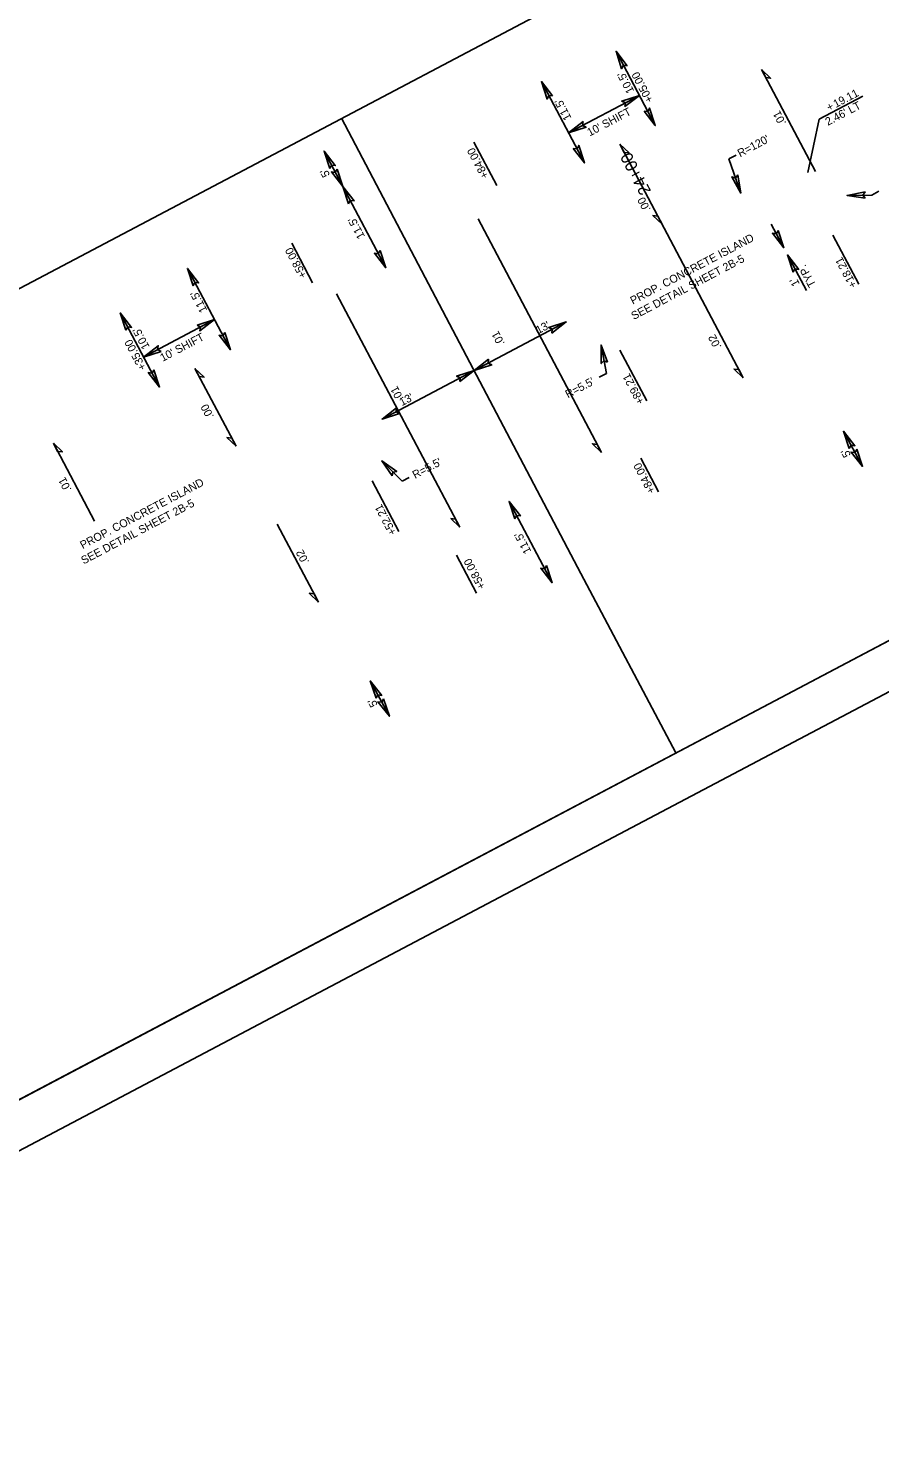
# Model space of a CAD drawing. Extents: x 1487555 to 1489555, y 497613 to 499367.
# Drawn here: x 1488347 to 1488773, y 497613 to 498320 of the extents above; entities that cross this region are included whole.
import ezdxf

# ---------------------------------------------------------------- set-up
doc = ezdxf.new("R2010")
doc.units = 0
for name, color, linetype in [('Old_Level_6', 7, 'Continuous'), ('Prop Dimension', 7, 'Continuous'), ('Prop Dimension Text', 7, 'Continuous'), ('Prop Horizontal Alignment Direction Label', 7, 'Continuous'), ('Prop Superelevation  Arrow CELL', 7, 'Continuous'), ('Prop Superelevation Label', 7, 'Continuous'), ('Prop Terminator CELL', 7, 'Continuous'), ('Sheet Plan CELL', 7, 'Continuous'), ('Sheet Plot Border Outside CELL', 7, 'Continuous')]:
    doc.layers.add(name, color=color, linetype=linetype)

msp = doc.modelspace()

# ---------------------------------------------------------------- linework, layer by layer
at = {"layer": 'Old_Level_6'}
msp.add_lwpolyline([(1488670.74, 497957.36), (1488623.31, 498047.13), (1488557.78, 498171.84), (1488503.78, 498274.53)], dxfattribs=at)
at = {"layer": 'Prop Dimension'}
for p, q in [((1488640.89, 498308.06), (1488660.5, 498270.92)), ((1488603.65, 498292.92), (1488625.13, 498252.24)), ((1488652.55, 498285.97), (1488617.18, 498267.29)), ((1488742.29, 498274.08), (1488764.2, 498285.65)), ((1488736.77, 498247.4), (1488742.29, 498274.08)), ((1488504.38, 498240.5), (1488495.04, 498258.19)), ((1488581.34, 498240.95), (1488569.88, 498262.64)), ((1488700.83, 498256.18), (1488697.3, 498254.31)), ((1488703.18, 498237.21), (1488697.3, 498254.31)), ((1488525.86, 498199.83), (1488504.38, 498240.5)), ((1488756.31, 498236.03), (1488768.66, 498236.19)), ((1488772.19, 498238.06), (1488768.66, 498236.19)), ((1488724.68, 498209.82), (1488718.44, 498221.65)), ((1488762.13, 498191.61), (1488749.17, 498216.17)), ((1488489.37, 498192.39), (1488478.95, 498212.13)), ((1488735.98, 498188.43), (1488726.55, 498206.28)), ((1488426.79, 498199.54), (1488448.27, 498158.86)), ((1488393.29, 498177.32), (1488412.9, 498140.18)), ((1488404.95, 498155.23), (1488440.32, 498173.91)), ((1488616.02, 498172.8), (1488570.04, 498148.52)), ((1488633.41, 498161.17), (1488636.06, 498146.98)), ((1488642.84, 498158.73), (1488656.23, 498133.38)), ((1488570.04, 498148.52), (1488524.05, 498124.24)), ((1488632.53, 498145.12), (1488636.06, 498146.98)), ((1488764.03, 498100.55), (1488754.52, 498118.14)), ((1488523.85, 498103.32), (1488534.07, 498093.13)), ((1488662.14, 498087.92), (1488653.26, 498104.73)), ((1488537.6, 498095), (1488534.07, 498093.13)), ((1488519.04, 498093.36), (1488532.43, 498068.01)), ((1488608.97, 498042.42), (1488587.49, 498083.1)), ((1488571.27, 498037.27), (1488561.29, 498056.17)), ((1488527.69, 497975.75), (1488518.17, 497993.35))]:
    msp.add_line(p, q, dxfattribs=at)
at = {"layer": 'Prop Superelevation  Arrow CELL'}
for p, q in [((1488740.5, 498247.92), (1488713.56, 498298.94)), ((1488704.45, 498144.86), (1488642.82, 498261.58)), ((1488633.71, 498107.5), (1488572.07, 498224.23)), ((1488562.96, 498070.15), (1488501.33, 498186.87)), ((1488451.13, 498110.61), (1488430.58, 498149.52)), ((1488380.39, 498073.26), (1488359.84, 498112.17)), ((1488492.22, 498032.79), (1488471.67, 498071.7))]:
    msp.add_line(p, q, dxfattribs=at)
for points in [[(1488713.56, 498298.94), (1488718.13, 498294.56), (1488715.72, 498294.85)], [(1488642.82, 498261.58), (1488647.39, 498257.21), (1488644.97, 498257.49)], [(1488663.92, 498221.61), (1488659.35, 498225.98), (1488661.76, 498225.7)], [(1488430.58, 498149.52), (1488435.15, 498145.15), (1488432.74, 498145.43)], [(1488704.45, 498144.86), (1488699.88, 498149.23), (1488702.29, 498148.95)], [(1488359.84, 498112.17), (1488364.41, 498107.79), (1488362, 498108.08)], [(1488451.13, 498110.61), (1488446.56, 498114.98), (1488448.97, 498114.7)], [(1488633.71, 498107.5), (1488629.14, 498111.87), (1488631.55, 498111.59)], [(1488562.96, 498070.15), (1488558.39, 498074.52), (1488560.8, 498074.24)], [(1488492.22, 498032.79), (1488487.65, 498037.16), (1488490.06, 498036.88)]]:
    msp.add_lwpolyline(points, close=True, dxfattribs=at)
at = {"layer": 'Prop Terminator CELL'}
for points in [[(1488646.46, 498300.83), (1488640.89, 498308.06), (1488643.7, 498299.31), (1488644.58, 498301.08)], [(1488609.22, 498285.69), (1488603.65, 498292.92), (1488606.46, 498284.17), (1488607.34, 498285.94)], [(1488645.32, 498280.4), (1488652.55, 498285.97), (1488643.8, 498283.16), (1488645.57, 498282.28)], [(1488654.93, 498278.16), (1488660.5, 498270.92), (1488657.69, 498279.67), (1488656.81, 498277.91)], [(1488624.42, 498272.87), (1488617.18, 498267.29), (1488625.93, 498270.1), (1488624.17, 498270.98)], [(1488497.87, 498249.51), (1488495.04, 498258.19), (1488500.68, 498250.93), (1488498.73, 498251.2)], [(1488619.56, 498259.48), (1488625.13, 498252.24), (1488622.32, 498260.99), (1488621.44, 498259.23)], [(1488501.55, 498249.19), (1488504.38, 498240.5), (1488498.74, 498247.76), (1488500.69, 498247.49)], [(1488701.72, 498246.22), (1488703.18, 498237.21), (1488698.72, 498245.25), (1488700.61, 498244.68)], [(1488507.21, 498231.82), (1488504.38, 498240.5), (1488510.02, 498233.25), (1488508.07, 498233.52)], [(1488765.33, 498234.6), (1488756.31, 498236.03), (1488765.34, 498237.75), (1488764.21, 498236.13)], [(1488721.85, 498218.5), (1488724.68, 498209.82), (1488719.04, 498217.08), (1488720.99, 498216.81)], [(1488523.03, 498208.51), (1488525.86, 498199.83), (1488520.22, 498207.08), (1488522.17, 498206.81)], [(1488729.38, 498197.6), (1488726.55, 498206.28), (1488732.19, 498199.03), (1488730.24, 498199.3)], [(1488429.62, 498190.85), (1488426.79, 498199.54), (1488432.43, 498192.28), (1488430.48, 498192.55)], [(1488396.12, 498168.64), (1488393.29, 498177.32), (1488398.93, 498170.07), (1488396.98, 498170.34)], [(1488431.64, 498171.08), (1488440.32, 498173.91), (1488433.07, 498168.27), (1488433.34, 498170.22)], [(1488608.79, 498167.23), (1488616.02, 498172.8), (1488607.27, 498169.99), (1488609.04, 498169.11)], [(1488445.44, 498167.54), (1488448.27, 498158.86), (1488442.63, 498166.11), (1488444.58, 498165.84)], [(1488413.63, 498158.06), (1488404.95, 498155.23), (1488412.21, 498160.87), (1488411.94, 498158.92)], [(1488636.59, 498152.6), (1488633.41, 498161.17), (1488633.5, 498151.98), (1488634.86, 498153.4)], [(1488577.27, 498154.09), (1488570.04, 498148.52), (1488578.79, 498151.33), (1488577.02, 498152.21)], [(1488410.07, 498148.86), (1488412.9, 498140.18), (1488407.26, 498147.44), (1488409.21, 498147.17)], [(1488562.8, 498142.95), (1488570.04, 498148.52), (1488561.29, 498145.71), (1488563.05, 498144.83)], [(1488531.29, 498129.81), (1488524.05, 498124.24), (1488532.8, 498127.05), (1488531.04, 498127.93)], [(1488757.43, 498109.49), (1488754.52, 498118.14), (1488760.23, 498110.94), (1488758.27, 498111.19)], [(1488761.11, 498109.2), (1488764.03, 498100.55), (1488758.32, 498107.75), (1488760.27, 498107.5)], [(1488529.13, 498095.87), (1488523.85, 498103.32), (1488531.39, 498098.06), (1488529.45, 498097.74)], [(1488590.32, 498074.42), (1488587.49, 498083.1), (1488593.13, 498075.84), (1488591.18, 498076.11)], [(1488606.14, 498051.1), (1488608.97, 498042.42), (1488603.33, 498049.68), (1488605.28, 498049.41)], [(1488521.09, 497984.69), (1488518.17, 497993.35), (1488523.89, 497986.15), (1488521.93, 497986.4)], [(1488524.77, 497984.41), (1488527.69, 497975.75), (1488521.97, 497982.95), (1488523.93, 497982.7)]]:
    msp.add_lwpolyline(points, close=True, dxfattribs=at)
at = {"layer": 'Sheet Plan CELL'}
for points in [[(1489039.06, 499339.23), (1487712.59, 498638.82), (1488202.86, 497710.31), (1489529.32, 498410.71)], [(1488202.86, 497710.31), (1487712.58, 498638.79), (1488862.13, 499245.82), (1488932.21, 499113.13), (1489109.11, 499206.52), (1489529.32, 498410.71)], [(1488035.48, 498027.26), (1489052.32, 498564.17), (1489219.68, 498247.22), (1488202.84, 497710.3)]]:
    msp.add_lwpolyline(points, close=True, dxfattribs=at)
at = {"layer": 'Sheet Plot Border Outside CELL'}
msp.add_lwpolyline([(1488066.15, 497612.67), (1489554.86, 498398.74), (1489043.57, 499367.04), (1487554.86, 498580.97)], close=True, dxfattribs=at)

# ---------------------------------------------------------------- texts
at = {"layer": 'Prop Dimension Text'}
for s, rotation, p in [("10.5'", 117.83509, (1488650.09, 498288.18)), ('+05.00', 117.83509, (1488659.68, 498283.64)), ('19.11', 27.83509, (1488750.69, 498279.65)), ("11.5'", 117.83509, (1488618.78, 498274.7)), ("10' SHIFT", 27.83509, (1488627.76, 498265.43)), ("2.46' LT", 27.83509, (1488746.7, 498270.75)), ('+', 27.83509, (1488747.35, 498277.88)), ("R=120'", 27.83509, (1488702.88, 498255)), ('+84.00', 117.83509, (1488577.53, 498245.66)), ("5'", 117.83509, (1488498.14, 498246.3)), ("11.5'", 117.83509, (1488515.6, 498215.52)), ('PROP. CONCRETE ISLAND', 27.83509, (1488649.29, 498181.37)), ('+58.00', 117.83509, (1488486.61, 498195.86)), ('SEE DETAIL SHEET 2B-5', 27.83509, (1488649.78, 498173.72)), ('TYP.', 117.83509, (1488740.94, 498191.34)), ('+18.21', 117.83509, (1488761.37, 498191.04)), ("1'", 117.83509, (1488732.77, 498191.8)), ("11.5'", 117.83509, (1488436.84, 498178.63)), ("13'", 27.83509, (1488602.1, 498166.61)), ("10.5'", 117.83509, (1488408.06, 498160.38)), ("10' SHIFT", 27.83509, (1488414.46, 498152.79)), ('+35.00', 117.83509, (1488406.4, 498149.9)), ("R=5.5'", 27.83509, (1488616.85, 498134.58)), ('+89.21', 117.83509, (1488655.2, 498132.84)), ("13'", 27.83509, (1488533.94, 498130.62)), ("R=5.5'", 27.83509, (1488540.52, 498094.28)), ('+84.00', 117.83509, (1488660.65, 498088.25)), ("5'", 117.83509, (1488758.34, 498106.3)), ('PROP. CONCRETE ISLAND', 27.83509, (1488374.5, 498059.17)), ('SEE DETAIL SHEET 2B-5', 27.83509, (1488375, 498051.52)), ('+52.21', 117.83509, (1488531.4, 498067.47)), ("11.5'", 117.83509, (1488598.71, 498058.12)), ('+58.00', 117.83509, (1488575.86, 498040.46)), ("5'", 117.83509, (1488522, 497981.5))]:
    msp.add_text(s, height=4, rotation=rotation, dxfattribs=at).set_placement(p)
at = {"layer": 'Prop Horizontal Alignment Direction Label'}
msp.add_text('24+00', height=6, rotation=117.83509, dxfattribs=at).set_placement((1488658.56, 498238.18))
at = {"layer": 'Prop Superelevation Label'}
for s, p in [('.01', (1488726.03, 498272.19)), ('.00', (1488658.35, 498229.05)), ('.01', (1488585.47, 498162.1)), ('.02', (1488693.7, 498160.4)), ('.01', (1488534.97, 498134.56)), ('.00', (1488440.22, 498125.63)), ('.01', (1488369.06, 498089.06)), ('.02', (1488487.8, 498052.88))]:
    msp.add_text(s, height=4, rotation=117.89497, dxfattribs=at).set_placement(p)

doc.saveas('drawing.dxf')
